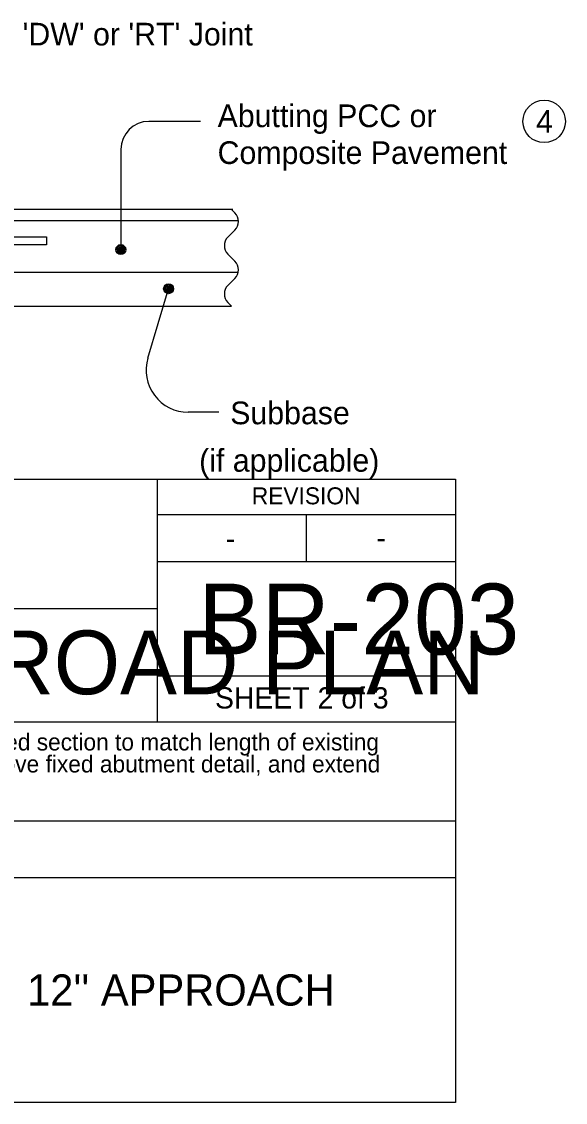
# Model space of a CAD drawing. Extents: x 10130 to 81668, y 5440 to 21644.
# Drawn here: x 16469 to 16853, y 10042 to 10805 of the extents above; entities that cross this region are included whole.
import ezdxf

# ---------------------------------------------------------------- set-up
doc = ezdxf.new("R2010")
doc.units = 0
for name, color, linetype in [('dsnStdBlock', 7, 'Continuous'), ('dsnStdBlockNotModified', 7, 'Continuous'), ('dsnStdBorder', 7, 'Continuous'), ('dsnStdLabel', 7, 'Continuous'), ('Level 2', 7, 'Continuous')]:
    doc.layers.add(name, color=color, linetype=linetype)

msp = doc.modelspace()

# ---------------------------------------------------------------- linework, layer by layer
at = {"layer": 'dsnStdBlock'}
for p, q in [((16446, 10672.29), (16617.71, 10672.29)), ((16446, 10664.25), (16621.73, 10664.25)), ((16405.9, 10652.8), (16486.09, 10652.8)), ((16486.09, 10652.8), (16486.09, 10647.23)), ((16486.09, 10647.23), (16405.9, 10647.23)), ((16620.74, 10627.74), (16446, 10627.74)), ((16446, 10603.98), (16616.75, 10603.98))]:
    msp.add_line(p, q, dxfattribs=at)
at = {"layer": 'dsnStdBlockNotModified'}
for p, q in [((16594.98, 10734.32), (16558.51, 10734.32)), ((16538.71, 10714.52), (16538.71, 10643.27)), ((16557.78, 10567.18), (16572.36, 10616.15)), ((16607.96, 10529.01), (16586.24, 10529.01))]:
    msp.add_line(p, q, dxfattribs=at)
for points in [[(16541.84, 10643.6), (16541.31, 10644.77), (16540.75, 10646.59), (16538.91, 10646.94), (16537.28, 10646.69), (16535.79, 10645.53), (16535.94, 10643.8), (16536.2, 10641.97), (16537.65, 10641.1), (16539.18, 10640.94), (16541.19, 10642.01), (16541.35, 10643.34), (16540.89, 10645.17), (16539.73, 10646.66), (16538, 10646.61), (16536.61, 10645.45), (16536.45, 10643.82), (16536.81, 10641.99), (16537.84, 10641.71), (16539.07, 10641.35), (16540.58, 10642.2), (16540.54, 10643.52), (16540.28, 10645.04), (16539.44, 10646.14), (16537.92, 10645.59), (16537.05, 10644.44), (16536.99, 10642.91), (16537.81, 10642.53), (16538.74, 10642.05), (16539.94, 10642.79), (16540.22, 10643.92), (16539.68, 10644.92), (16538.56, 10645), (16537.76, 10644.46), (16537.48, 10643.44), (16537.9, 10642.94), (16538.53, 10642.65), (16539.42, 10643.19), (16539.6, 10643.9), (16539.17, 10644.61), (16538.57, 10644.49), (16538.18, 10643.97), (16538.2, 10643.25), (16538.71, 10643.27), (16538.99, 10643.89)], [(16572.63, 10619.33), (16571.46, 10618.81), (16569.64, 10618.24), (16569.29, 10616.4), (16569.54, 10614.78), (16570.71, 10613.28), (16572.43, 10613.43), (16574.26, 10613.69), (16575.13, 10615.14), (16575.3, 10616.68), (16574.22, 10618.68), (16572.89, 10618.85), (16571.07, 10618.39), (16569.57, 10617.22), (16569.62, 10615.49), (16570.79, 10614.1), (16572.42, 10613.94), (16574.24, 10614.3), (16574.52, 10615.33), (16574.89, 10616.56), (16574.03, 10618.07), (16572.71, 10618.03), (16571.19, 10617.78), (16570.09, 10616.93), (16570.64, 10615.42), (16571.79, 10614.54), (16573.32, 10614.48), (16573.7, 10615.31), (16574.19, 10616.23), (16573.44, 10617.44), (16572.31, 10617.71), (16571.31, 10617.17), (16571.24, 10616.05), (16571.77, 10615.25), (16572.8, 10614.97), (16573.3, 10615.39), (16573.58, 10616.02), (16573.05, 10616.91), (16572.33, 10617.1), (16571.62, 10616.67), (16571.74, 10616.06), (16572.27, 10615.67), (16572.98, 10615.69), (16572.96, 10616.2), (16572.35, 10616.49)]]:
    msp.add_lwpolyline(points, dxfattribs=at)
for centre in [(16538.66, 10643.87), (16572.36, 10616.16)]:
    msp.add_circle(centre, 3.47, dxfattribs=at)
for centre, radius, start, end in [((16558.51, 10714.52), 19.8, 90, 180), ((16586.25, 10558.71), 29.7, 163.41722, 270)]:
    msp.add_arc(centre, radius, start, end, dxfattribs=at)
at = {"layer": 'dsnStdBorder'}
for p, q in [((16619.25, 10669.69), (16616.75, 10672.19)), ((16614.26, 10652.64), (16619.25, 10657.64)), ((16616.75, 10638.08), (16614.26, 10640.58)), ((16619.25, 10635.59), (16616.75, 10638.08)), ((16614.26, 10618.53), (16619.25, 10623.53)), ((16616.75, 10603.98), (16614.26, 10606.48))]:
    msp.add_line(p, q, dxfattribs=at)
for centre, start, end in [((16613.22, 10663.67), 315, 45), ((16620.29, 10646.61), 135, 225), ((16613.22, 10629.56), 315, 45), ((16620.29, 10612.51), 135, 225)]:
    msp.add_arc(centre, 8.53, start, end, dxfattribs=at)
at = {"layer": 'dsnStdLabel'}
for p, q in [((16564.2, 10481.87), (16564.2, 10390.52)), ((16564.2, 10456.92), (16775.12, 10456.92)), ((16669.66, 10456.92), (16669.66, 10423.72)), ((16564.2, 10423.72), (16775.12, 10423.72)), ((16087.1, 10390.52), (16564.2, 10390.52)), ((16564.2, 10390.52), (16564.2, 10310.52)), ((16775.12, 10342.72), (16564.2, 10342.72)), ((16087.1, 10310.52), (16775.12, 10310.52)), ((16087.1, 10240.52), (16775.12, 10240.52)), ((16087.1, 10200.52), (16775.12, 10200.52)), ((16087.1, 10200.52), (16775.12, 10200.52))]:
    msp.add_line(p, q, dxfattribs=at)
msp.add_lwpolyline([(16087.1, 10481.87), (16775.12, 10481.87), (16775.12, 10041.86), (16087.1, 10041.86)], close=True, dxfattribs=at)
at = {"layer": 'Level 2'}
msp.add_circle((16837.62, 10734.32), 15, dxfattribs=at)

# ---------------------------------------------------------------- texts
at = {"layer": 'dsnStdBlockNotModified'}
for s, p in [("'DW' or 'RT' Joint", (16469.27, 10787.9)), ('Abutting PCC or', (16607, 10730.26)), ('Composite Pavement', (16607, 10704.26)), ('Subbase', (16615.9, 10520.54)), ('(if applicable)', (16593.96, 10487.03))]:
    msp.add_text(s, height=16, dxfattribs=at).set_placement(p)
at = {"layer": 'dsnStdLabel'}
for s, height, p in [('REVISION', 12, (16631.18, 10464.01)), ('-', 15, (16612.69, 10432.5)), ('-', 15, (16719.23, 10432.97)), ('BR-203', 50, (16593.38, 10358.05)), ('STANDARD ROAD PLAN', 45.0011, (16100.14, 10329.94)), ('SHEET 2 of 3', 15, (16605.15, 10319.88)), ('Revised to extend non-reinforced section to match length of existing ', 12, (16238.42, 10290.26)), ('PCC approach pavement, remove fixed abutment detail, and extend ', 12, (16238.42, 10274.73)), ("DOUBLE REINFORCED 12'' APPROACH", 22, (16140.6, 10110.19))]:
    msp.add_text(s, height=height, dxfattribs=at).set_placement(p)
at = {"layer": 'Level 2'}
msp.add_text('4', height=16, dxfattribs=at).set_placement((16831.95, 10726.32))

doc.saveas('drawing.dxf')
